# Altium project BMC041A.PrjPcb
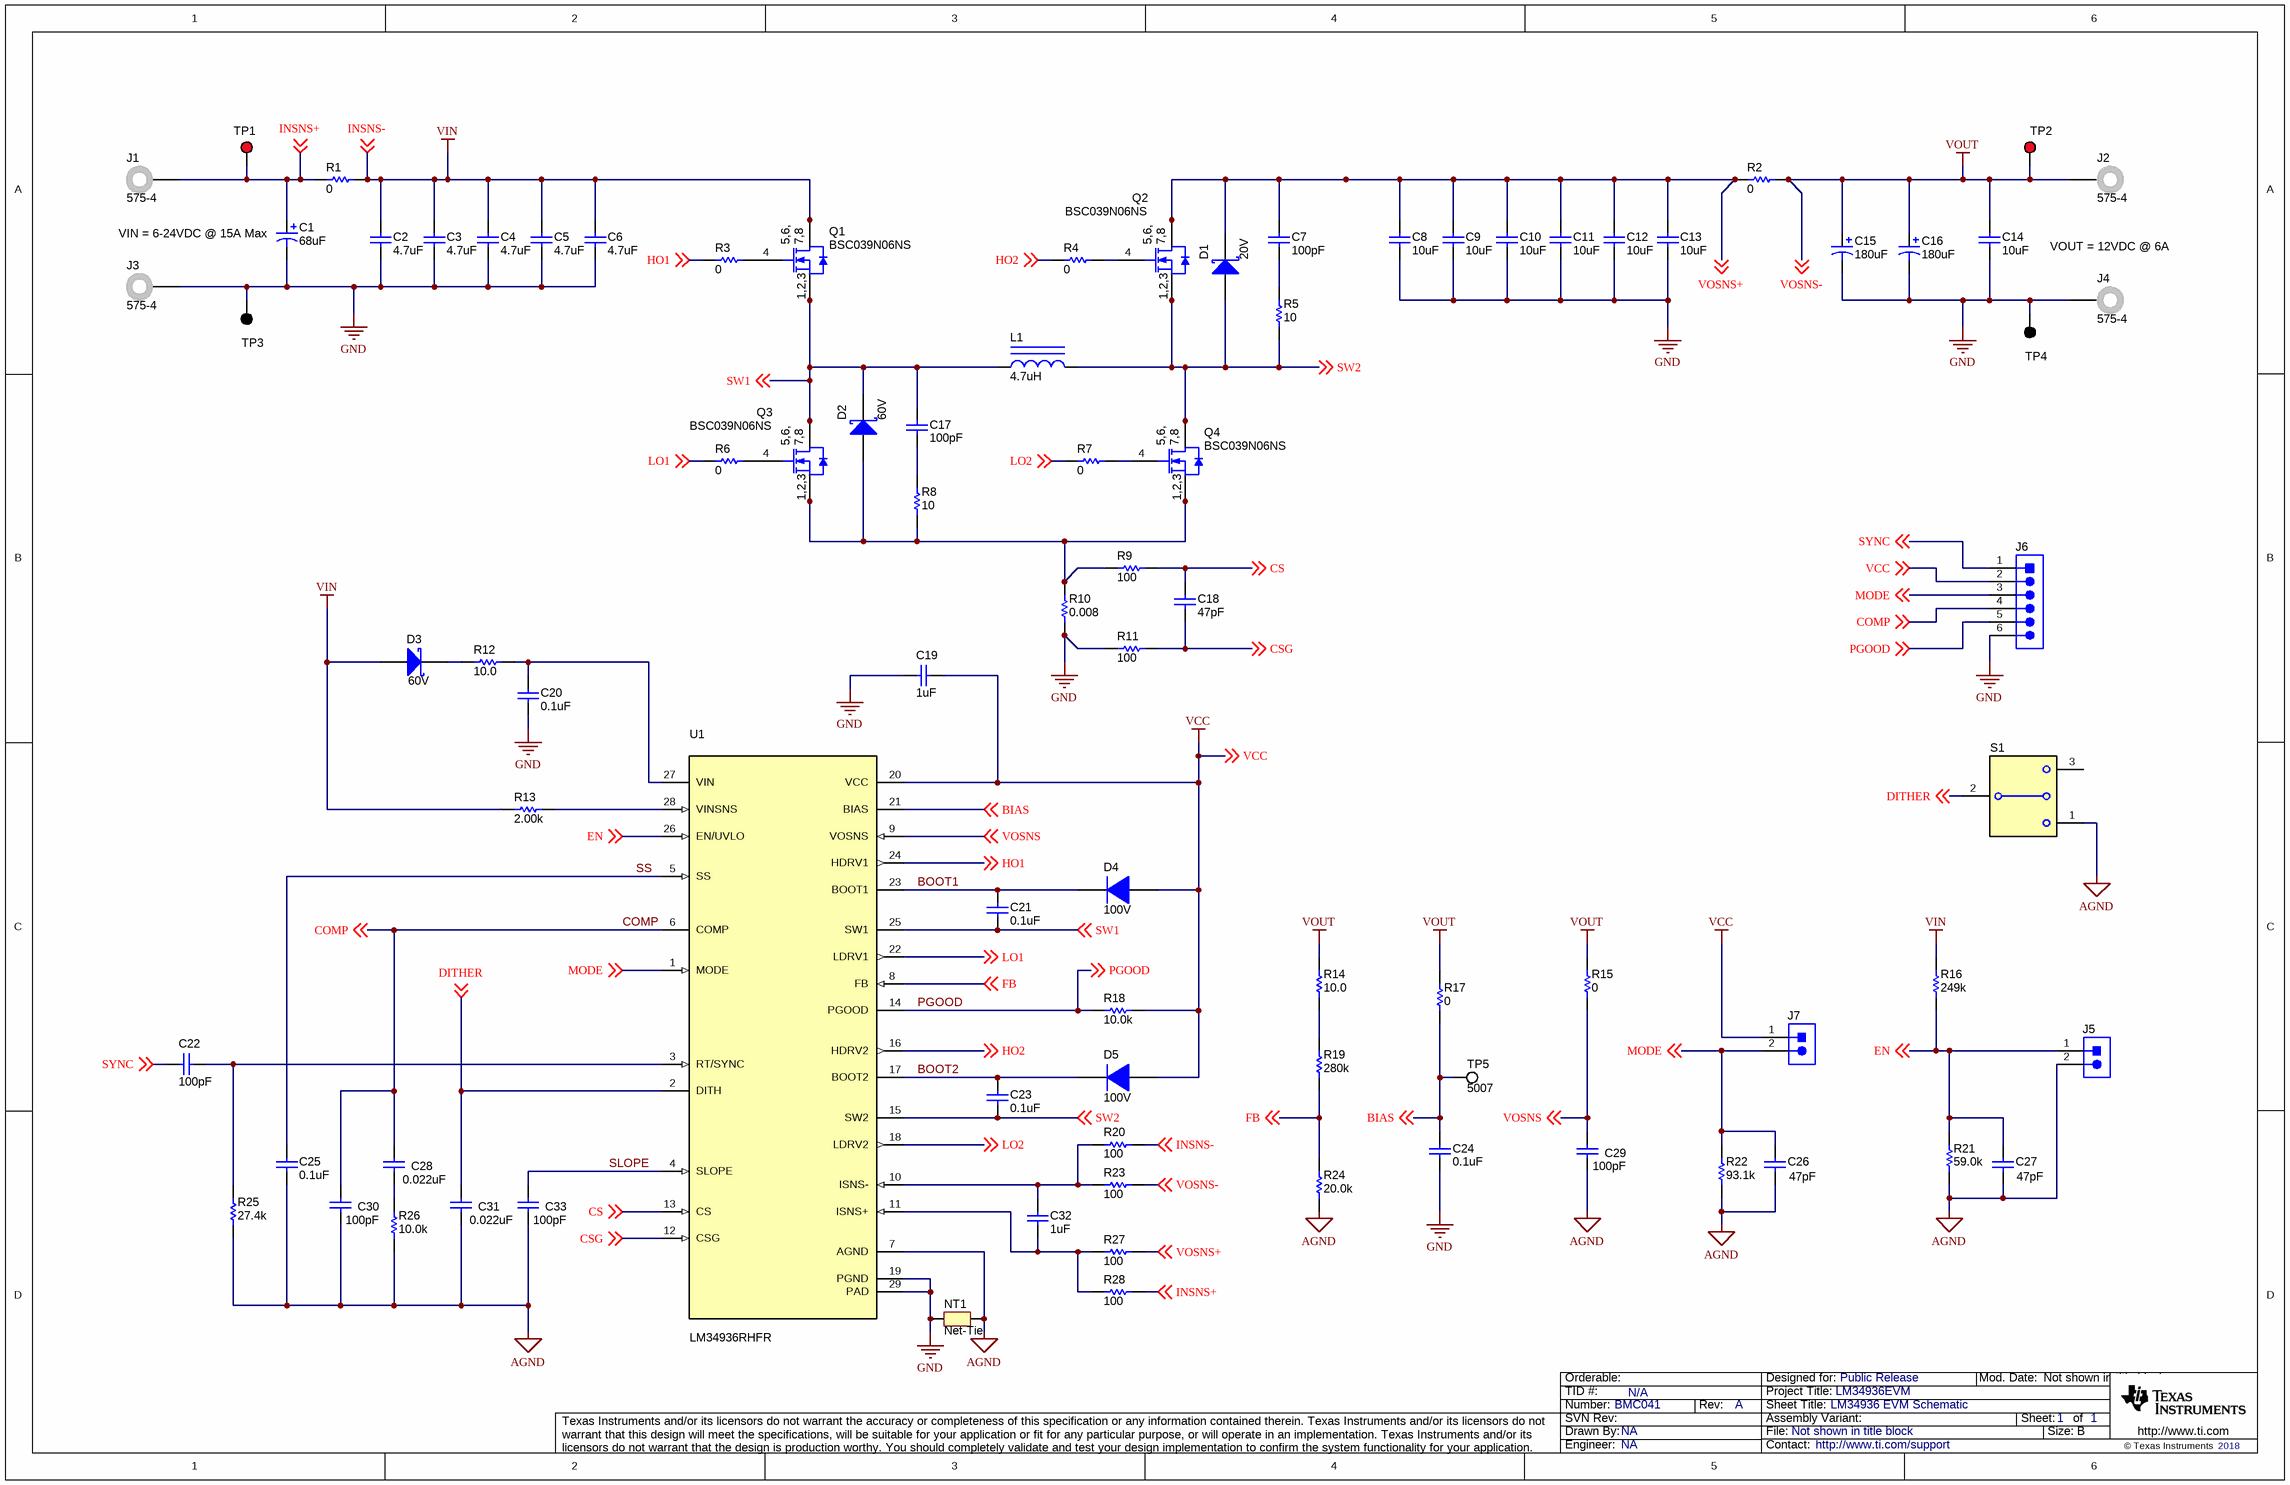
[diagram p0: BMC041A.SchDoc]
TID: N/A; TechSupport: http://www.ti.com/support; SCH_Rev: A; PRJ_Title: LM34936EVM; PRJ_Number: BMC041; PRJ_Engineer: NA; PRJ_Customer: Public Release; PCB_Rev: A; PCB_Layout: NA; CopyrightYear: 2018
2 sheets, 108 parts. Net scope: global (net labels, ports and power ports of the same name join across sheets).
Board file: BMC041A.PcbDoc
Sheets:
  BMC041A.SchDoc
  BMC041A-HW.SchDoc

## Sheet BMC041A.SchDoc: LM34936 EVM Schematic
size 431 x 279 mm; Date: Not shown in title block; ApprovedBy: Not shown in title block; CheckedBy: Not shown in title block; Author: Not shown in title block; CompanyName: Not shown in title block; DrawnBy: NA; Engineer: Not shown in title block; Organization: Not shown in title block; Address1: Not shown in title block; Address2: Not shown in title block; Address3: Not shown in title block; Address4: Not shown in title block; DocumentNumber: 1; Revision: Use project parameter SCH_Rev; SheetNumber: 1; SheetTotal: 1; PageSetup: Record=PageOptions¦CenterHorizontal=True¦CenterVertical=True¦PrintScale=1.00¦XCorrection=1.00¦YCorrection=1.00¦PrintKind=0¦BorderSize=5000000¦LeftOffset=0¦BottomOffset=0¦Orientation=2¦PaperLength=1000¦PaperWidth=1000¦Scale=100¦PaperSource=15¦PrintQuality=600¦MediaType=1¦DitherType=10¦PaperKind=Letter¦PrintScaleMode=1

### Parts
C1  ValueDisplayed: 68uF  [CR_1000x1000]  (hidden comment: Cap_Polarized)
C2  ValueDisplayed: 4.7uF  [1210_220]  (hidden comment: Capacitor)
C3  ValueDisplayed: 4.7uF  [1210_220]  (hidden comment: Capacitor)
C4  ValueDisplayed: 4.7uF  [1210_220]  (hidden comment: Capacitor)
C5  ValueDisplayed: 4.7uF  [1210_220]  (hidden comment: Capacitor)
C6  ValueDisplayed: 4.7uF  [1210_220]  (hidden comment: Capacitor)
C7  ValueDisplayed: 100pF  [1206]  (hidden comment: Capacitor)
C8  ValueDisplayed: 10uF  [1210_270]  (hidden comment: Capacitor)
C9  ValueDisplayed: 10uF  [1210_270]  (hidden comment: Capacitor)
C10  ValueDisplayed: 10uF  [1210_270]  (hidden comment: Capacitor)
C11  ValueDisplayed: 10uF  [1210_270]  (hidden comment: Capacitor)
C12  ValueDisplayed: 10uF  [1210_270]  (hidden comment: Capacitor)
C13  ValueDisplayed: 10uF  [1210_270]  (hidden comment: Capacitor)
C14  ValueDisplayed: 10uF  [1210_270]  (hidden comment: Capacitor)
C15  ValueDisplayed: 180uF  [CR_1000x1270]  (hidden comment: Cap_Polarized)
C16  ValueDisplayed: 180uF  [CR_1000x1270]  (hidden comment: Cap_Polarized)
C17  ValueDisplayed: 100pF  [1206]  (hidden comment: Capacitor)
C18  ValueDisplayed: 47pF  [0603L]  (hidden comment: Capacitor)
C19  ValueDisplayed: 1uF  [0603]  (hidden comment: Capacitor)
C20  ValueDisplayed: 0.1uF  [0603L]  (hidden comment: Capacitor)
C21  ValueDisplayed: 0.1uF  [0603_HV]  (hidden comment: Capacitor)
C22  ValueDisplayed: 100pF  [0603L]  (hidden comment: Capacitor)
C23  ValueDisplayed: 0.1uF  [0603_HV]  (hidden comment: Capacitor)
C24  ValueDisplayed: 0.1uF  [0603]  (hidden comment: Capacitor)
C25  ValueDisplayed: 0.1uF  [0603L]  (hidden comment: Capacitor)
C26  47pF  [0603L]
C27  47pF  [0603L]
C28  ValueDisplayed: 0.022uF  [0603L]  (hidden comment: Capacitor)
C29  ValueDisplayed: 100pF  [0603L]  (hidden comment: Capacitor)
C30  ValueDisplayed: 100pF  [0603L]  (hidden comment: Capacitor)
C31  ValueDisplayed: 0.022uF  [0603L]  (hidden comment: Capacitor)
C32  ValueDisplayed: 1uF  [0603L]  (hidden comment: Capacitor)
C33  ValueDisplayed: 100pF  [0603L]  (hidden comment: Capacitor)
D1  20V  [SMA]
D2  60V  [SMA]
D3  60V  [SOD-323F]
D4  100V  [SOD-323]
D5  100V  [SOD-323]
J1  575-4  [Keystone_575-4]
J2  575-4  [Keystone_575-4]
J3  575-4  [Keystone_575-4]
J4  575-4  [Keystone_575-4]
J5  Header_2x1  [Sullins_PBC02SAAN]  (value not drawn)
J6  PBC06SAAN  [Sullins_PxC06SAAN]  (value not drawn)
J7  Header_2x1  [Sullins_PBC02SAAN]  (value not drawn)
L1  ValueDisplayed: 4.7uH  [XAL1510]  (hidden comment: Inductor_Iron)
NT1  Net-Tie  [Net-Tie_10mil]  (net tie, no BOM)
Q1  BSC039N06NS  [PG-TDSON-8]
Q2  BSC039N06NS  [PG-TDSON-8]
Q3  BSC039N06NS  [PG-TDSON-8]
Q4  BSC039N06NS  [PG-TDSON-8]
R1  ValueDisplayed: 0  [2512_WIDE_VISHAY]  (hidden comment: Resistor)
R2  ValueDisplayed: 0  [2512_WIDE_VISHAY]  (hidden comment: Resistor)
R3  value 0  [0603L]  (hidden comment: Resistor)
R4  value 0  [0603L]  (hidden comment: Resistor)
R5  ValueDisplayed: 10  [1206]  (hidden comment: Resistor)
R6  value 0  [0603L]  (hidden comment: Resistor)
R7  value 0  [0603L]  (hidden comment: Resistor)
R8  ValueDisplayed: 10  [1206]  (hidden comment: Resistor)
R9  value 100  [0603L]  (hidden comment: Resistor)
R10  ValueDisplayed: 0.008  [3015]  (hidden comment: Resistor)
R11  value 100  [0603L]  (hidden comment: Resistor)
R12  value 10.0  [0603L]  (hidden comment: Resistor)
R13  ValueDisplayed: 2.00k  [0603L]  (hidden comment: CRCW06032K00FKEA)
R14  value 10.0  [0603L]  (hidden comment: Resistor)
R15  value 0  [0603L]  (hidden comment: Resistor)
R16  value 249k  [0603L]  (hidden comment: Resistor)
R17  value 0  [0603L]  (hidden comment: Resistor)
R18  value 10.0k  [0603L]  (hidden comment: Resistor)
R19  value 280k  [0603L]  (hidden comment: Resistor)
R20  ValueDisplayed: 100  [0603L]  (hidden comment: Resistor)
R21  value 59.0k  [0603L]  (hidden comment: Resistor)
R22  ValueDisplayed: 93.1k  [0603L]  (hidden comment: Resistor)
R23  ValueDisplayed: 100  [0603L]  (hidden comment: Resistor)
R24  value 20.0k  [0603L]  (hidden comment: Resistor)
R25  ValueDisplayed: 27.4k  [0603L]  (hidden comment: CRCW060327K4FKEA)
R26  value 10.0k  [0603L]  (hidden comment: Resistor)
R27  ValueDisplayed: 100  [0603L]  (hidden comment: Resistor)
R28  ValueDisplayed: 100  [0603L]  (hidden comment: Resistor)
S1  SW_SPDT_ON-OFF-ON_COM2_1_3  [SW_CJS_1201A]  (value not drawn)
TP1  5005  [Keystone5005]  (value not drawn)
TP2  5005  [Keystone5005]  (value not drawn)
TP3  5006  [Keystone5006]  (value not drawn)
TP4  5006  [Keystone5006]  (value not drawn)
TP5  5007  [Keystone5007]
U1  LM34936RHFR  [RHF0028A]

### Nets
AGND: C25.2 C26.2 C27.2 C29.2 C30.2 C31.2 C33.2 J5.2 NT1.2 R21.1 R22.1 R24.1 R25.1 R26.1 S1.1 U1.7(AGND)
GND: C1.2(-) C2.2 C3.2 C4.2 C5.2 C6.2 C8.2 C9.2 C10.2 C11.2 C12.2 C13.2 C14.2 C15.2(-) C16.2(-) C19.1 C20.2 C24.2 J3.1 J4.1 J6.6 NT1.1 R10.1 R11.2 TP3.1 TP4.1 U1.19(PGND) U1.29(PAD)
VCC: C19.2 D4.2(A) D5.2(A) J6.2 J7.1 R18.2 U1.20(VCC) ; off-sheet VCC
VIN: C2.1 C3.1 C4.1 C5.1 C6.1 D3.2(A) Q1.5(D) Q1.6(D) Q1.7(D) Q1.8(D) Q1.9(D) R1.2 R13.2 R16.2 R20.2 ; off-sheet INSNS-  [also labelled INSNS-]
VOUT: C14.1 C15.1(+) C16.1(+) J2.1 R2.2 R14.1 R15.1 R17.1 R23.2 TP2.1 ; off-sheet VOSNS-  [also labelled VOSNS-]
BIAS: C24.1 R17.2 TP5.1 U1.21(BIAS) ; off-sheet BIAS
BOOT1: C21.2 D4.1(K) U1.23(BOOT1)
BOOT2: C23.1 D5.1(K) U1.17(BOOT2)
COMP: C28.1 C30.1 J6.4 U1.6(COMP) ; off-sheet COMP
CS: C18.1 R9.1 U1.13(CS) ; off-sheet CS
CSG: C18.2 R11.1 U1.12(CSG) ; off-sheet CSG
DITHER: C31.1 S1.2(COM) U1.2(DITH) ; off-sheet DITHER
EN: C27.1 J5.1 R16.1 R21.2 U1.26(EN/UVLO) ; off-sheet EN
FB: R19.1 R24.2 U1.8(FB) ; off-sheet FB
HO1: R3.2 U1.24(HDRV1) ; off-sheet HO1
HO2: R4.2 U1.16(HDRV2) ; off-sheet HO2
INSNS+: C1.1(+) J1.1 R1.1 R28.2 TP1.1 ; off-sheet INSNS+
LO1: R6.2 U1.22(LDRV1) ; off-sheet LO1
LO2: R7.2 U1.18(LDRV2) ; off-sheet LO2
MODE: C26.1 J6.3 J7.2 R22.2 U1.1(MODE) ; off-sheet MODE
PGOOD: J6.5 R18.1 U1.14(PGOOD) ; off-sheet PGOOD
SLOPE: C33.1 U1.4(SLOPE)
SS: C25.1 U1.5(SS)
SW1: C17.1 C21.1 D2.1(K) L1.1 Q1.1(S) Q1.2(S) Q1.3(S) Q3.5(D) Q3.6(D) Q3.7(D) Q3.8(D) Q3.9(D) U1.25(SW1) ; off-sheet SW1
SW2: C23.2 D1.2(A) L1.2 Q2.1(S) Q2.2(S) Q2.3(S) Q4.5(D) Q4.6(D) Q4.7(D) Q4.8(D) Q4.9(D) R5.1 U1.15(SW2) ; off-sheet SW2
SYNC: C22.1 J6.1 ; off-sheet SYNC
VOSNS: C29.1 R15.2 U1.9(VOSNS) ; off-sheet VOSNS
VOSNS+: C7.1 C8.1 C9.1 C10.1 C11.1 C12.1 C13.1 D1.1(K) Q2.5(D) Q2.6(D) Q2.7(D) Q2.8(D) Q2.9(D) R2.1 R27.2 ; off-sheet VOSNS+
NetC7_2: C7.2 R5.2
NetC17_2: C17.2 R8.2
NetC20_1: C20.1 R12.1 U1.27(VIN)
NetC22_2: C22.2 R25.2 U1.3(RT/SYNC)
NetC28_2: C28.2 R26.2
NetC32_1: C32.1 R20.1 R23.1 U1.10(ISNS-)
NetC32_2: C32.2 R27.1 R28.1 U1.11(ISNS+)
NetD2_2: D2.2(A) Q3.1(S) Q3.2(S) Q3.3(S) Q4.1(S) Q4.2(S) Q4.3(S) R8.1 R9.2 R10.2
NetD3_1: D3.1(K) R12.2
NetQ1_4: Q1.4(G) R3.1
NetQ2_4: Q2.4(G) R4.1
NetQ3_4: Q3.4(G) R6.1
NetQ4_4: Q4.4(G) R7.1
NetR13_1: R13.1 U1.28(VINSNS)
NetR14_2: R14.2 R19.2

Not connected (* = marked no-connect by the designer): S1 3

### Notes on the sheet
- (near C1) VIN = 6-24VDC @ 15A Max
- VOUT = 12VDC @ 6A

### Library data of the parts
C1 = CMP-0012275-3: CAP, Aluminum Polymer, 68 uF, 63 V, +/- 20%, 0.028 ohm, 2-Pin SMD, Body 10.3 x 10.3 mm, Height 10 mm SMD; PartNumber: PCR1J680MCL1GS; Manufacturer: Nichicon; Polarized: Y; CompType: Capacitor; Value: 68uF; Cap_F: 68µF; VDC_V: 63V; ESR_ohm: 0.028; IRMS_A: 2.8A; TaMin_C: -55°C; TaMax_C: 125°C; Cap_Case: 10x10; AEC Category: Q200; AEC Qualified: N; SizeArea_mm2: 100; SizeAreaWB_mm2: 144; SizeX_mm: 10
C2 = CMP-0009134-2: CAP, CERM, 4.7 uF, 100 V, +/- 10%, X7S, 1210; PartNumber: C3225X7S2A475K200AB; Manufacturer: TDK; Polarized: N; Value: 4.7uF; U/M: EA; Cap_F: 4.7µF; ESR_ohm: 4.236m; Value1: 0.004236 ohm; VDC_V: 100V; IRMS_A: 3.57337A; TaMin_C: -55°C; TaMax_C: 125°C; AEC Category: Q200; SizeArea_mm2: 8; SizeAreaWB_mm2: 14.7; SizeX_mm: 3.2; SizeY_mm: 2.5; SizeZ_mm: 2.2
C3-C6 = CMP-0009134-2: CAP, CERM, 4.7 uF, 100 V, +/- 10%, X7S, 1210; PartNumber: C3225X7S2A475K200AB; Manufacturer: TDK; Value: 4.7uF; U/M: EA; VDC_V: 100V; Polarized: N; Cap_F: 4.7µF; ESR_ohm: 4.236m; Value1: 0.004236 ohm; IRMS_A: 3.57337A; TaMin_C: -55°C; TaMax_C: 125°C; AEC Category: Q200; SizeArea_mm2: 8; SizeAreaWB_mm2: 14.7; SizeX_mm: 3.2; SizeY_mm: 2.5; SizeZ_mm: 2.2
C7 C17 = CMP-0008462-2: CAP, CERM, 100 pF, 100 V, +/- 5%, C0G/NP0, 1206; PartNumber: 12061A101JAT2A; Manufacturer: AVX; Polarized: N; Value: 100pF; U/M: EA; ESR_ohm: 7.01d; Value1: 0.701 ohm; VDC_V: 100V; TaMin_C: -55°C; TaMax_C: 125°C; AEC Category: Q200; SizeArea_mm2: 5.12; SizeAreaWB_mm2: 10.92; SizeX_mm: 3.2; SizeY_mm: 1.6; SizeZ_mm: 1.35
C8-C13 = CMP-0009226-3: CAP, CERM, 10 uF, 50 V, +/- 10%, X7R, 1210; PartNumber: GRM32ER71H106KA12L; Manufacturer: MuRata; Value: 10uF; U/M: EA; VDC_V: 50V; Polarized: N; Cap_F: 10µF; Value1: Unknown; TaMin_C: -55°C; TaMax_C: 125°C; Cap_Case: 1210; AEC Category: Q200; SizeArea_mm2: 8; SizeAreaWB_mm2: 14.7; SizeX_mm: 3.2; SizeY_mm: 2.5; SizeZ_mm: 2.7
C14 = CMP-0009226-3: CAP, CERM, 10 uF, 50 V, +/- 10%, X7R, 1210; PartNumber: GRM32ER71H106KA12L; Manufacturer: MuRata; Polarized: N; Value: 10uF; U/M: EA; Cap_F: 10µF; Value1: Unknown; VDC_V: 50V; TaMin_C: -55°C; TaMax_C: 125°C; Cap_Case: 1210; AEC Category: Q200; SizeArea_mm2: 8; SizeAreaWB_mm2: 14.7; SizeX_mm: 3.2; SizeY_mm: 2.5; SizeZ_mm: 2.7
C15 C16 = CMP-0012273-3: CAP, Aluminum Polymer, 180 uF, 50 V, +/- 20%, 0.019 ohm, SMD, 2-Leads, Dia 10.5mm, Pin Spacing 8mm SMD; PartNumber: PCR1H181MCL1GS; Manufacturer: Nichicon; CompType: Capacitor; Value: 180uF; VDC_V: 50V; ESR_ohm: 0.019; Polarized: Y; Cap_F: 180µF; IRMS_A: 3.5A; TaMin_C: -55°C; TaMax_C: 125°C; Cap_Case: 10x12.7mm; AEC Category: Q200; AEC Qualified: N
C18 = CMP-0007220-4: CAP, CERM, 47 pF, 50 V, +/- 5%, C0G/NP0, 0603; PartNumber: GRM1885C1H470JA01D; Manufacturer: MuRata; Polarized: N; Value: 47pF; U/M: EA; Value1: Unknown; VDC_V: 50V; TaMin_C: -55°C; TaMax_C: 125°C; Cap_Case: 0603; AEC Category: Q200; SizeArea_mm2: 1.28; SizeAreaWB_mm2: 4.68; SizeX_mm: 1.6; SizeY_mm: 0.8; SizeZ_mm: 1
C19 = CMP-0007405-4: CAP, CERM, 1 uF, 25 V, +/- 10%, X7R, 0603; PartNumber: GRM188R71E105KA12D; Manufacturer: MuRata; Polarized: N; Value: 1uF; U/M: EA; Cap_F: 1µF; Value1: Unknown; VDC_V: 25V; TaMin_C: -55°C; TaMax_C: 125°C; AEC Category: Q200; SizeArea_mm2: 1.28; SizeAreaWB_mm2: 4.68; SizeX_mm: 1.6; SizeY_mm: 0.8; SizeZ_mm: 1
C20 C21 C23 C25 = CMP-0007469-4: CAP, CERM, 0.1 uF, 100 V, +/- 10%, X7R, 0603; PartNumber: GRM188R72A104KA35D; Manufacturer: MuRata; Polarized: N; Value: 0.1uF; U/M: EA; Cap_F: 100nF; Value1: Unknown; VDC_V: 100V; TaMin_C: -55°C; TaMax_C: 125°C; Cap_Case: 0603; AEC Category: Q200; SizeArea_mm2: 1.28; SizeAreaWB_mm2: 4.68; SizeX_mm: 1.6; SizeY_mm: 0.8; SizeZ_mm: 1
C22 C29 C30 C33 = CMP-0007237-4: CAP, CERM, 100 pF, 100 V, +/- 5%, C0G/NP0, 0603; PartNumber: GRM1885C2A101JA01D; Manufacturer: MuRata; Polarized: N; Value: 100pF; U/M: EA; Value1: Unknown; VDC_V: 100V; TaMin_C: -55°C; TaMax_C: 125°C; Cap_Case: 0603; AEC Category: Q200; SizeArea_mm2: 1.28; SizeAreaWB_mm2: 4.68; SizeX_mm: 1.6; SizeY_mm: 0.8; SizeZ_mm: 1
C24 = CMP-0007469-4: CAP, CERM, 0.1 uF, 100 V, +/- 10%, X7R, 0603; PartNumber: GRM188R72A104KA35D; Manufacturer: MuRata; Polarized: N; Value: 0.1uF; U/M: EA; Cap_F: 100nF; Value1: Unknown; VDC_V: 100V; TaMin_C: -55°C; TaMax_C: 125°C; AEC Category: Q200; SizeArea_mm2: 1.28; SizeAreaWB_mm2: 4.68; SizeX_mm: 1.6; SizeY_mm: 0.8; SizeZ_mm: 1
C26 C27 = CMP-0007220-4: CAP, CERM, 47 pF, 50 V, +/- 5%, C0G/NP0, 0603; PartNumber: GRM1885C1H470JA01D; Manufacturer: MuRata; Polarized: N; CompType: Capacitor; U/M: EA; Value1: Unknown; VDC_V: 50V; TaMin_C: -55°C; TaMax_C: 125°C; Cap_Case: 0603; AEC Category: Q200; SizeArea_mm2: 1.28; SizeAreaWB_mm2: 4.68; SizeX_mm: 1.6; SizeY_mm: 0.8; SizeZ_mm: 1
C28 C31 = CMP-0006901-4: CAP, CERM, 0.022 uF, 50 V, +/- 10%, X7R, 0603; PartNumber: C0603C223K5RACTU; Manufacturer: Kemet; Polarized: N; U/M: EA; Cap_F: 22nF; Value1: Unknown; VDC_V: 50V; TaMin_C: -55°C; TaMax_C: 125°C; Cap_Case: 0603; AEC Category: Q200; SizeArea_mm2: 1.28; SizeAreaWB_mm2: 4.68; SizeX_mm: 1.6; SizeY_mm: 0.8; SizeZ_mm: 1
C32 = CMP-0007405-4: CAP, CERM, 1 uF, 25 V, +/- 10%, X7R, 0603; PartNumber: GRM188R71E105KA12D; Manufacturer: MuRata; Polarized: N; Value: 1uF; U/M: EA; Cap_F: 1µF; Value1: Unknown; VDC_V: 25V; TaMin_C: -55°C; TaMax_C: 125°C; Cap_Case: 0603; AEC Category: Q200; SizeArea_mm2: 1.28; SizeAreaWB_mm2: 4.68; SizeX_mm: 1.6; SizeY_mm: 0.8; SizeZ_mm: 1
D1 = CMP-0077009-1: Diode, Schottky, 20 V, 5 A, SMA; PartNumber: RSX501L-20TE25; Manufacturer: Rohm; U/M: EA; Vf_V: 3.9dV; Value1: 5A; Value2: 0.39V; TJmax_C: 125°C; AEC Category: Q101; Green_Lifecycle: Not Set; Green_REACh: Incomplete; SizeArea_mm2: 16.3228; SizeAreaWB_mm2: 37.3428; SizeX_mm: 5.59; SizeY_mm: 2.92; SizeZ_mm: 2.87
D2 = CMP-0077010-1: Diode, Schottky, 60 V, 3 A, SMA; PartNumber: RB050L-60TE25; Manufacturer: Rohm; U/M: EA; Vf_V: 5.6dV; Value1: 3A; Value2: 0.56V; TJmax_C: 150°C; AEC Category: Q101; Green_Lifecycle: Not Set; Green_REACh: Incomplete; SizeArea_mm2: 16.3228; SizeAreaWB_mm2: 37.3428; SizeX_mm: 5.59; SizeY_mm: 2.92; SizeZ_mm: 2.87
D3 = CMP-0077011-1: Diode, Schottky, 60 V, 1 A, SOD-323F; PartNumber: PMEG6010CEJ,115; Manufacturer: Nexperia; U/M: EA; Vf_V: 6.6dV; Value1: 1A; Value2: 0.66V; TJmax_C: 150°C; AEC Category: Q101; Green_Lifecycle: Not Set; Green_REACh: Incomplete; SizeArea_mm2: 3.125; SizeAreaWB_mm2: 7.875; SizeX_mm: 2.5; SizeY_mm: 1.25; SizeZ_mm: 0.8
D4 D5 = CMP-0029006-1: Diode, Ultrafast, 100 V, 0.25 A, SOD-323; Manufacturer: Nexperia; PartNumber: BAS316,115; U/M: EA; Io_A: 2.5dA; Vf_V: 1.4V; Value1: 0.25A; TJmax_C: 150°C; AEC Category: Q101; Green_Lifecycle: Not Set; Green_REACh: Incomplete; SizeArea_mm2: 3.645; SizeAreaWB_mm2: 8.695; SizeX_mm: 2.7; SizeY_mm: 1.35; SizeZ_mm: 1
J1-J4 = CMP-0055165-2: Standard Banana Jack, Uninsulated, 5.5mm; Manufacturer: Keystone; CT: TRUE; Green_REACh: Passed; CNHeader: FALSE; Green_Lifecycle: Active
J5 J7 = CMP-0054566-1: Header, 100mil, 2x1, Gold, TH; PartNumber: PBC02SAAN; Manufacturer: Sullins Connector Solutions; Cert_UL: Y; CNHeader: TRUE; CT: FALSE; Current_A: 3A; Gender: Male; Green_Lifecycle: Active; Green_REACh: Passed; Pitch_mm: 2.54; Row_Count: 1; Shrouded: N; Voltage_V: 1.8kV
J6 = CMP-0054603-1: Header, 2.54mm, 6x1, Gold, TH; Manufacturer: Sullins Connector Solutions; CNHeader: TRUE; Current_A: 3A; Green_Lifecycle: Not Set; Shrouded: N; Gender: Male; Green_REACh: Incomplete; Row_Count: 1; Pitch_mm: 2.54; CT: FALSE; Cert_UL: Y
L1 = CMP-0060970-1: Inductor, Shielded, Composite, 4.7 uH, 29 A, 0.00335 ohm, SMD; Manufacturer: Coilcraft; PartNumber: XAL1510-472MEB; DCR_ohm: 3.35m; Value: 4.7uH; Ind_H: 4.7µH; Imax_A: 29A; Irms: 29A @ 40C rise; Isat: 39A @ 30% inductance drop; AEC Category: Q200; Green_Lifecycle: Not Set; Green_REACh: Incomplete; SizeArea_mm2: 252.56; SizeAreaWB_mm2: 320.16; SizeX_mm: 16.4; SizeY_mm: 15.4; SizeZ_mm: 10
NT1 = CMP-0078142-2: Single point connection between nets.
Q1-Q4 = CMP-0000784-1: MOSFET, N-CH, 60 V, 19 A, PG-TDSON-8; Alternate Manufacturer: None; Manufacturer: Infineon Technologies; SizeZ_mm: 1.12; ChType: N; Value2: 27 nC; VdsMax_V: 60V; SizeX_mm: 5.99; SizeY_mm: 4.9; Vgs_V: 20V; QgTyp_nC: 27; Value: 60V; SizeArea_mm2: 29.351; AEC Category: Q101; IdsMax_A: 19A; SizeAreaWB_mm2: 55.131; U/M: EA
R1 = CMP-0015368-2: RES, 0, 5%, 2 W, 2512 WIDE; PartNumber: RCL12250000Z0EG; Manufacturer: Vishay Draloric; Value: 0; Value_Code: 0000; Power_W: 2W; TempCo: ppm/C; EIA_Code: E24; U/M: EA; AEC Category: Q200
R2 = CMP-0015368-2: RES, 0, 5%, 2 W, 2512 WIDE; Manufacturer: Vishay Draloric; PartNumber: RCL12250000Z0EG; U/M: EA; Value: 0; Power_W: 2W; TempCo: ppm/C; Value_Code: 0000; EIA_Code: E24; AEC Category: Q200
R3 R4 R6 R7 R15 R17 = CMP-0025885-5: RES, 0, 5%, 0.1 W, 0603; PartNumber: RC0603JR-070RL; Manufacturer: Yageo; Value_Code: 0000; Power_W: 100mW; Value2: 0.1W; VDC_V: 75V; TempCo: 200 ppm/C; EIA_Code: E24; AEC Category: Q200; AEC Qualified: N; SizeArea_mm2: 1.28; SizeAreaWB_mm2: 4.68; SizeX_mm: 1.6; SizeY_mm: 0.8; SizeZ_mm: 1
R5 R8 = CMP-0018578-3: RES, 10, 5%, 0.25 W, AEC-Q200 Grade 0, 1206; PartNumber: CRCW120610R0JNEA; Manufacturer: Vishay-Dale; Value: 10; Value_Code: 10R0; Power_W: 250mW; Value2: 0.25W; VDC_V: 200V; TempCo: 200 ppm/C; EIA_Code: E24; AEC Category: Q200; AEC Grade: 0; AEC Qualified: Y; SizeArea_mm2: 5.12; SizeX_mm: 3.2; SizeY_mm: 1.6; SizeZ_mm: 1.35
R9 R11 = CMP-0022736-4: RES, 100, 1%, 0.1 W, 0603; PartNumber: RC0603FR-07100RL; Manufacturer: Yageo; Value_Code: 100R; Power_W: 100mW; Value2: 0.1W; VDC_V: 75V; TempCo: 100 ppm/C; EIA_Code: E96; AEC Category: Q200; AEC Qualified: N; SizeArea_mm2: 1.28; SizeAreaWB_mm2: 4.68; SizeX_mm: 1.6; SizeY_mm: 0.8; SizeZ_mm: 1
R10 = CMP-0015114-2: RES, 0.008, 1%, 4 W, 3015 WIDE; PartNumber: KRL7638-C-R008-F-T1; Manufacturer: Susumu Co Ltd; Value: 0.008; Power_W: 4W; TempCo: 50 ppm/C; U/M: EA; Res_ohm: 8m; Value_Code: 8L000; EIA_Code: E96; AEC Category: Q200; SizeArea_mm2: 28.88; SizeAreaWB_mm2: 55.68; SizeX_mm: 7.6; SizeY_mm: 3.8; SizeZ_mm: 0.7
R12 R14 = CMP-0022751-4: RES, 10.0, 1%, 0.1 W, 0603; PartNumber: RC0603FR-0710RL; Manufacturer: Yageo; Res_ohm: 10; Value_Code: 10R0; Power_W: 100mW; Value2: 0.1W; VDC_V: 75V; TempCo: 100 ppm/C; EIA_Code: E96; AEC Category: Q200; AEC Qualified: N; SizeArea_mm2: 1.28; SizeAreaWB_mm2: 4.68; SizeX_mm: 1.6; SizeY_mm: 0.8; SizeZ_mm: 1
R13 = CMP-0022268-4: RES, 2.00 k, 1%, 0.1 W, AEC-Q200 Grade 0, 0603; Manufacturer: Vishay-Dale; CompType: Resistor; Value: 2.00k; Res_ohm: 2k; Value_Code: 2k00; Power_W: 100mW; Value2: 0.1W; VDC_V: 75V; TempCo: 100 ppm/C; EIA_Code: E96; AEC Category: Q200; AEC Grade: 0; AEC Qualified: Y; SizeArea_mm2: 1.28; SizeX_mm: 1.6; SizeY_mm: 0.8; SizeZ_mm: 1
R16 = CMP-0022941-4: RES, 249 k, 1%, 0.1 W, 0603; PartNumber: RC0603FR-07249KL; Manufacturer: Yageo; Power_W: 100mW; Value2: 0.1W; VDC_V: 75V; TempCo: 100 ppm/C; EIA_Code: E96; AEC Category: Q200; AEC Qualified: N; SizeArea_mm2: 1.28; SizeAreaWB_mm2: 4.68; SizeX_mm: 1.6; SizeY_mm: 0.8; SizeZ_mm: 1
R18 R26 = CMP-0022746-5: RES, 10.0 k, 1%, 0.1 W, 0603; PartNumber: RC0603FR-0710KL; Manufacturer: Yageo; Res_ohm: 10k; Value_Code: 10k0; Power_W: 100mW; Value2: 0.1W; VDC_V: 75V; TempCo: 100 ppm/C; EIA_Code: E96; AEC Category: Q200; AEC Qualified: N; SizeArea_mm2: 1.28; SizeAreaWB_mm2: 4.68; SizeX_mm: 1.6; SizeY_mm: 0.8; SizeZ_mm: 1
R19 = CMP-0022969-4: RES, 280 k, 1%, 0.1 W, 0603; PartNumber: RC0603FR-07280KL; Manufacturer: Yageo; Power_W: 100mW; Value2: 0.1W; VDC_V: 75V; TempCo: 100 ppm/C; EIA_Code: E96; AEC Category: Q200; AEC Qualified: N; SizeArea_mm2: 1.28; SizeAreaWB_mm2: 4.68; SizeX_mm: 1.6; SizeY_mm: 0.8; SizeZ_mm: 1
R20 R23 R27 R28 = CMP-0021991-4: RES, 100, 1%, 0.1 W, AEC-Q200 Grade 0, 0603; PartNumber: CRCW0603100RFKEA; Manufacturer: Vishay-Dale; Value: 100; Value_Code: 100R; Power_W: 100mW; Value2: 0.1W; VDC_V: 75V; TempCo: 100 ppm/C; EIA_Code: E96; AEC Category: Q200; AEC Grade: 0; AEC Qualified: Y; SizeArea_mm2: 1.28; SizeX_mm: 1.6; SizeY_mm: 0.8; SizeZ_mm: 1
R21 = CMP-0023195-5: RES, 59.0 k, 1%, 0.1 W, 0603; PartNumber: RC0603FR-0759KL; Manufacturer: Yageo; Res_ohm: 59k; Value_Code: 59k0; Power_W: 100mW; Value2: 0.1W; VDC_V: 75V; TempCo: 100 ppm/C; EIA_Code: E96; AEC Category: Q200; AEC Qualified: N; SizeArea_mm2: 1.28; SizeAreaWB_mm2: 4.68; SizeX_mm: 1.6; SizeY_mm: 0.8; SizeZ_mm: 1
R22 = CMP-0023322-5: RES, 93.1 k, 1%, 0.1 W, 0603; PartNumber: RC0603FR-0793K1L; Manufacturer: Yageo; Value: 93.1k; Value_Code: 93k1; Power_W: 100mW; Value2: 0.1W; VDC_V: 75V; TempCo: 100 ppm/C; EIA_Code: E96; AEC Category: Q200; AEC Qualified: N; SizeArea_mm2: 1.28; SizeAreaWB_mm2: 4.68; SizeX_mm: 1.6; SizeY_mm: 0.8; SizeZ_mm: 1
R24 = CMP-0022906-5: RES, 20.0 k, 1%, 0.1 W, 0603; PartNumber: RC0603FR-0720KL; Manufacturer: Yageo; Res_ohm: 20k; Value_Code: 20k0; Power_W: 100mW; Value2: 0.1W; VDC_V: 75V; TempCo: 100 ppm/C; EIA_Code: E96; AEC Category: Q200; AEC Qualified: N; SizeArea_mm2: 1.28; SizeAreaWB_mm2: 4.68; SizeX_mm: 1.6; SizeY_mm: 0.8; SizeZ_mm: 1
R25 = CMP-0022254-4: RES, 27.4 k, 1%, 0.1 W, AEC-Q200 Grade 0, 0603; Manufacturer: Vishay-Dale; CompType: Resistor; Value: 27.4k; Value_Code: 27k4; Power_W: 100mW; Value2: 0.1W; VDC_V: 75V; TempCo: 100 ppm/C; EIA_Code: E96; AEC Category: Q200; AEC Qualified: Y; AEC Grade: 0; SizeArea_mm2: 1.28; SizeX_mm: 1.6; SizeY_mm: 0.8; SizeZ_mm: 1
S1 = CMP-0002159-2: Slide SW, SPDT 0.1A 50VDC; PartNumber: CJS-1201TA; Manufacturer: Copal Electronics; VDC_V: 50V; PositionCount: 1; CurrentRating_mA: 100A; CompType: Switch
TP1 TP2 = CMP-0055142-1: Test Point, Compact, Red, TH; Manufacturer: Keystone; CNHeader: FALSE; ContactFinish: Silver; CT: TRUE; Green_Lifecycle: Active; Green_REACh: Passed
TP3 TP4 = CMP-0055143-1: Test Point, Compact, Black, TH; Manufacturer: Keystone; CNHeader: FALSE; ContactFinish: Silver; CT: TRUE; Green_Lifecycle: Active; Green_REACh: Passed
TP5 = CMP-0055144-1: Test Point, Compact, White, TH; Manufacturer: Keystone; CNHeader: FALSE; ContactFinish: Silver; CT: TRUE; Green_Lifecycle: Active; Green_REACh: Passed
U1 = CMP-0084180-1: 30-V Wide VIN Synchronous 4-Switch Buck-Boost Controller, RHF0028A (VQFN-28); Manufacturer: Texas Instruments; Alternate PartNumber: LM34936RHFT; SizeX_mm: 4; SizeY_mm: 5; CompType: IC; SizeZ_mm: 1; SizeArea_mm2: 20; SizeAreaWB_mm2: 42; AEC Category: Q200; AEC Qualified: N

## Sheet BMC041A-HW.SchDoc: LM34936 EVM Hardware Page
size 431 x 279 mm; Date: Not shown in title block; ApprovedBy: Not shown in title block; CheckedBy: Not shown in title block; Author: Not shown in title block; CompanyName: Not shown in title block; DrawnBy: NA; Engineer: Not shown in title block; Organization: Not shown in title block; Address1: Not shown in title block; Address2: Not shown in title block; Address3: Not shown in title block; Address4: Not shown in title block; DocumentNumber: 1; Revision: Use project parameter SCH_Rev; SheetNumber: 1; SheetTotal: 1; PageSetup: Record=PageOptions¦CenterHorizontal=True¦CenterVertical=True¦PrintScale=1.00¦XCorrection=1.00¦YCorrection=1.00¦PrintKind=0¦BorderSize=5000000¦LeftOffset=0¦BottomOffset=0¦Orientation=2¦PaperLength=1000¦PaperWidth=1000¦Scale=100¦PaperSource=15¦PrintQuality=600¦MediaType=1¦DitherType=10¦PaperKind=Letter¦PrintScaleMode=1
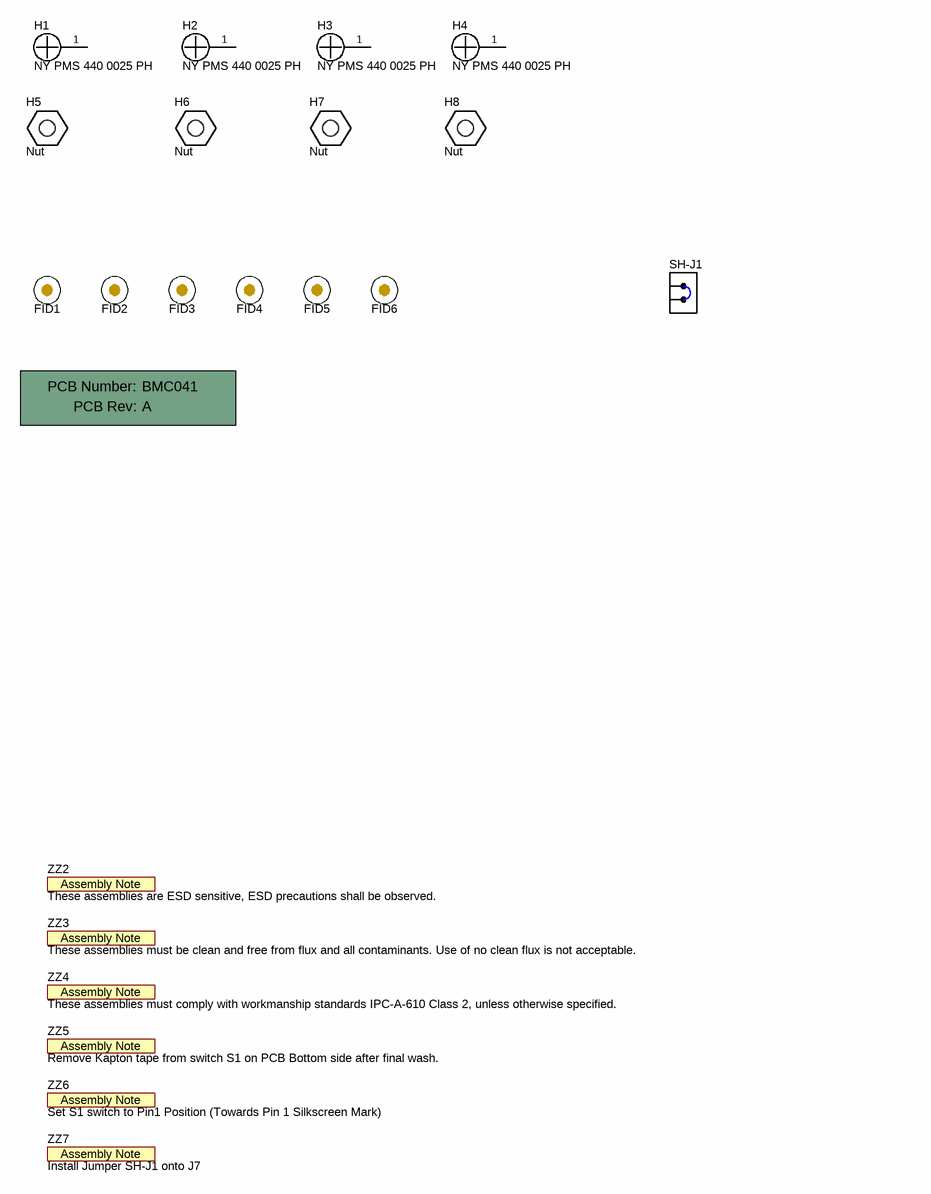
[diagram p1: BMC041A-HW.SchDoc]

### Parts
!PCB1  Printed Circuit Board  (value not drawn)  (mechanical)
FID1  Fiducial  [Fiducial10-20]  (value not drawn)
FID2  Fiducial  [Fiducial10-20]  (value not drawn)
FID3  Fiducial  [Fiducial10-20]  (value not drawn)
FID4  Fiducial  [Fiducial10-20]  (value not drawn)
FID5  Fiducial  [Fiducial10-20]  (value not drawn)
FID6  Fiducial  [Fiducial10-20]  (value not drawn)
H1  NY PMS 440 0025 PH  [NY PMS 440 0025 PH]
H2  NY PMS 440 0025 PH  [NY PMS 440 0025 PH]
H3  NY PMS 440 0025 PH  [NY PMS 440 0025 PH]
H4  NY PMS 440 0025 PH  [NY PMS 440 0025 PH]
H5  Nut  [Keystone_1902C]
H6  Nut  [Keystone_1902C]
H7  Nut  [Keystone_1902C]
H8  Nut  [Keystone_1902C]
SH-J1  M7582-05  [Harwin_M7582-05]  (value not drawn)  (mechanical)
ZZ2  These assemblies are ESD sensitive, ESD precautions shall be observed.  [AssemblyNote]  (no BOM)
ZZ3  These assemblies must be clean and free from flux and all contaminants. Use of no clean flux is not acceptable.  [AssemblyNote]  (no BOM)
ZZ4  These assemblies must comply with workmanship standards IPC-A-610 Class 2, unless otherwise specified.  [AssemblyNote]  (no BOM)
ZZ5  Remove Kapton tape from switch S1 on PCB Bottom side after final wash.  [AssemblyNote]  (no BOM)
ZZ6  Set S1 switch to Pin1 Position (Towards Pin 1 Silkscreen Mark)  [AssemblyNote]  (no BOM)
ZZ7  Install Jumper SH-J1 onto J7  [AssemblyNote]  (no BOM)

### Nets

Not connected (* = marked no-connect by the designer): H1 1; H2 1; H3 1; H4 1

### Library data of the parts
!PCB1 = CMP-0003618-2: Manufacturer: Any; PartNumber: BMC041
FID1-FID6 = CMP-0077181-1: Fiducial mark.  There is nothing to buy or mount.
H1-H4 = CMP-0003617-1: Machine Screw, Round, #4-40 x 1/4, Nylon, Philips panhead; Manufacturer: B&F Fastener Supply; CompType: Hardware
H5-H8 = CMP-0003610-1: Standoff, Hex, 0.5"L #4-40 Nylon; Manufacturer: Keystone; PartNumber: 1902C; CompType: Hardware
SH-J1 = CMP-0078738-1: Single Operation 2.54mm Pitch Open Top Jumper Socket; Manufacturer: Harwin; CompType: Shunt
ZZ2 = CMP-0077236-1
ZZ3 = CMP-0077237-1
ZZ4 = CMP-0077238-1
ZZ5-ZZ7 = AssemblyNote: SymbolCreator: codlsc

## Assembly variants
001: not fitted FID1 FID2 FID3 FID4 FID5 FID6 R20 R28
